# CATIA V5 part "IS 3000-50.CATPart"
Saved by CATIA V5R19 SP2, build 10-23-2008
Part number: IS 3000-50
Bounding box of the stored display mesh (mm): x -47.487 to 47.487, y -47.487 to 47.487, z 0 to 220
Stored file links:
  C:\Users\Bora\Desktop\3D Katı model\IS serisi\IS 3000\IS 3000-50.CATPart
  C:\Program Files\Dassault Systemes\B19\intel_a\reffiles\standard\MetricThickPitch.txt
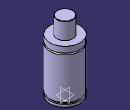
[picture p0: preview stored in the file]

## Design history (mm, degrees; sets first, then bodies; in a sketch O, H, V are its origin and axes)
Body1 (main body)
  Sketch1 on yz-plane, origin (0, 0, 0), H (0, 1, 0), V (0, 0, 1)
    point P1 (47.5, 148.5)
    point P2 (47.5, 143.5)
    point P5 (25, 219)
    point P7 (25, 219)
    point P12 (47.5, 143.5)
    point P13 (47.5, 148.5)
    arc A1 centre (47.5, 146) radius 2.5 from (47.5, 148.5) to (47.5, 143.5) ccw
    line L1 (47.5, 0) -> (47.5, 8)
    line L2 (25, 219) -> (25, 167)
    arc A2 centre (24, 219) radius 1 from (25, 219) to (24, 220) ccw
    line L3 (43.5, 13) -> (43.5, 8)
    line L4 (47.5, 13) -> (47.5, 143.5)
    line L5 (47.5, 148.5) -> (47.5, 167)
    line L6 (24, 220) -> (0, 220)
    line L7 (25, 167) -> (47.5, 167)
    line L8 (0, 0) -> (47.5, 0)
    line L9 (43.5, 8) -> (47.5, 8)
    line L10 (43.5, 13) -> (47.5, 13)
    tangency: L6 A2
    horizontal: L7 H, L8 H, L9 H, L10 H
    coincidence: P1 P13, P2 P12, P5 P7
  Shaft1: profile Sketch1, axis Sketch1.V, angle 360
  Sketch2 on face of Shaft1 from Sketch1.L8, origin (0, 0, 0), H (1, 0, 0), V (0, -1, 0)
    point P1 (30, 0)
    distance P1 V = 30
  Hole1: placed by Sketch2, at (30, 0, 0) direction (0, 0, 1), diameter 6.647, depth 13, threaded "M8", thread diameter 8, thread depth 13, pitch 1.25
  CircPattern1: of Hole1, instances 4, angular step 90, axis from xy-plane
